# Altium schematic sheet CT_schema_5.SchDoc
size 256 x 245 mm
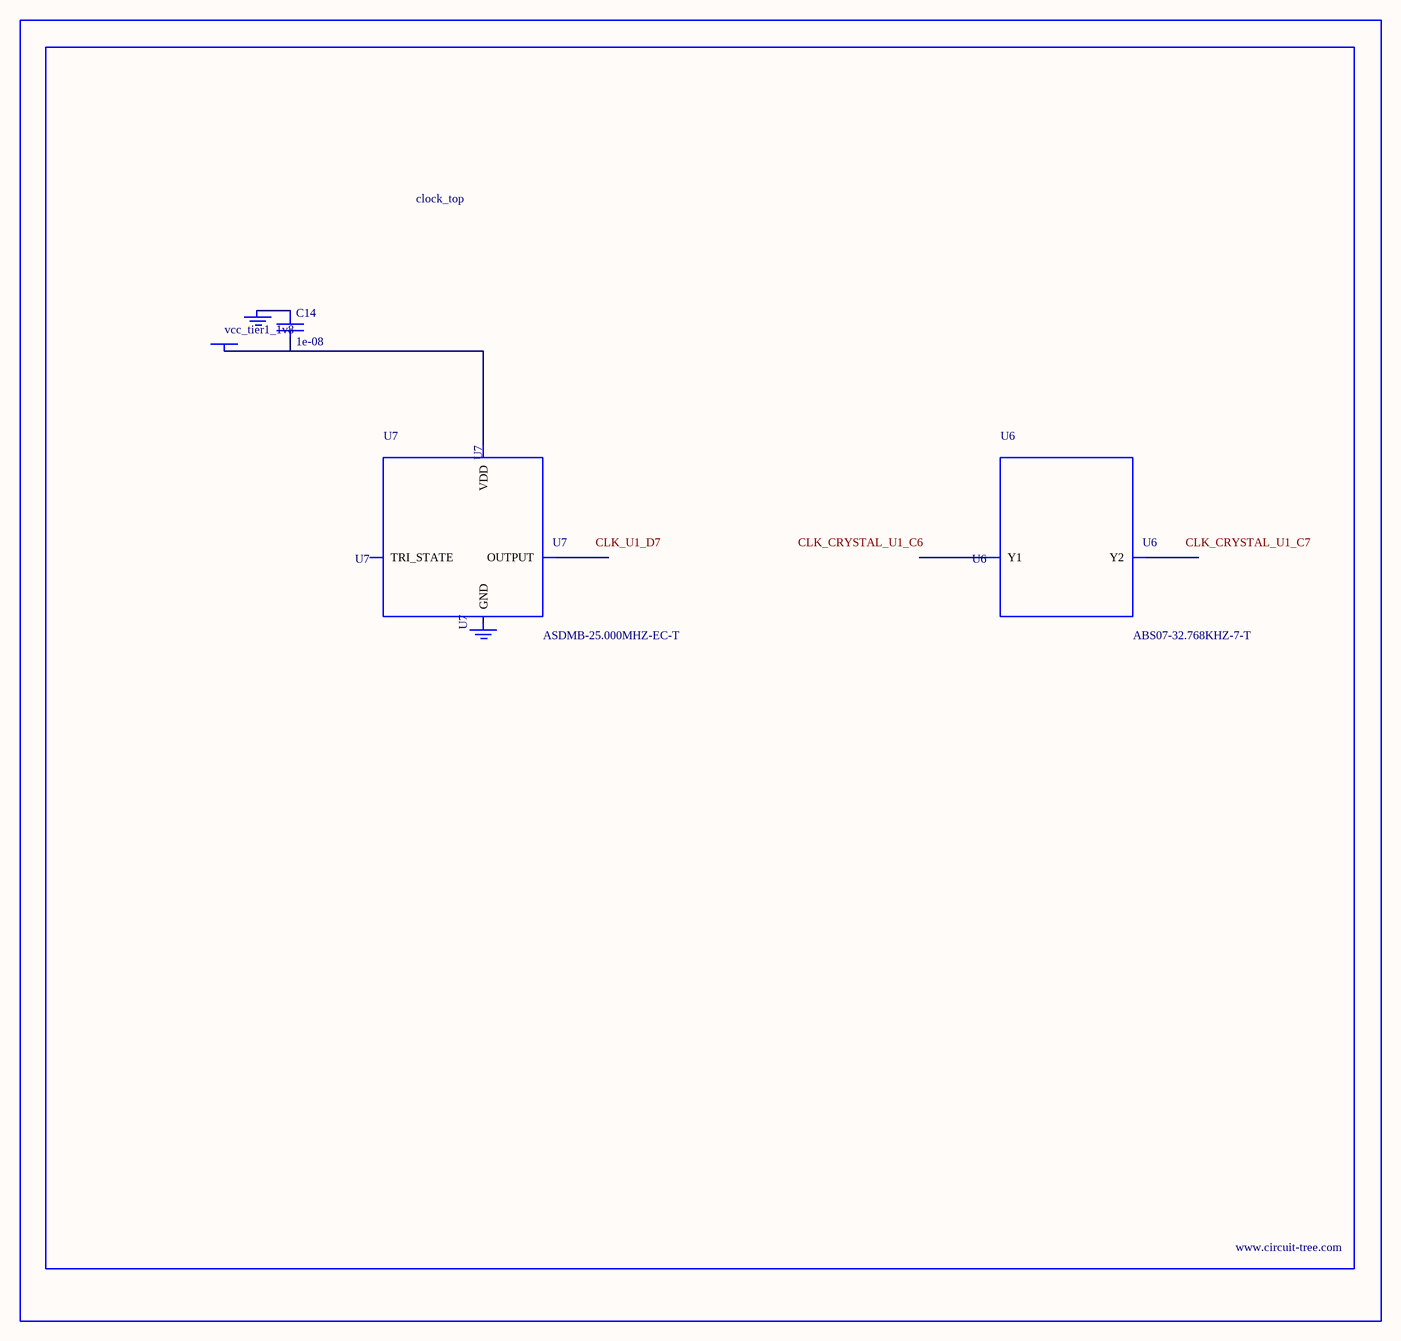
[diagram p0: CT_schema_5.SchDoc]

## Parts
BORDER4  (no value)
C14  1e-08  [C0402]
GND_INSTANCE_4_0  (no value)
GND_INSTANCE_4_1  (no value)
POWER_INSTANCE_4_0  vcc_tier1_1v8
U6  ABS07-32.768KHZ-7-T  [ABS07-32.768KHZ-7-T]
U7  ASDMB-25.000MHZ-EC-T  [ASDMB-XX.XXXXMHZ-XX-XX-XXX]

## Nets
NetC14_1: C14.1 GND_INSTANCE_4_0.0(GND)
NetC14_2: C14.2 POWER_INSTANCE_4_0.0(PWR) U7.4(VDD)

Not connected (* = marked no-connect by the designer): GND_INSTANCE_4_1 0(GND); U6 1(Y1) 2(Y2); U7 1(TRI_STATE) 2(GND) 3(OUTPUT)

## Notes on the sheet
- Labels drawn without touching a wire or pin: CLK_CRYSTAL_U1_C6, CLK_CRYSTAL_U1_C7, CLK_U1_D7

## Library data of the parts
BORDER4 = BORDER_PAGE4
C14 = C0402C103K3RAC
GND_INSTANCE_4_0 GND_INSTANCE_4_1 = GND
POWER_INSTANCE_4_0 = PWR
